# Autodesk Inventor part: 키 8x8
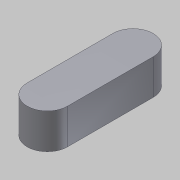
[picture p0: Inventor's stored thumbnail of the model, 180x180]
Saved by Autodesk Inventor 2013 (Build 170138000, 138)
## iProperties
Company: 한국ATC센터
Created: 2014-11
Part Number: 키 8x8
Document SubType Name: Modeling
Designer: KYOUNG IL JANG
Density: 7.86 g/cm^3
Material: Steel, Mild
Mass: 10.2483 g
Surface Area: 7.8646 cm^2
Volume: 1.30386 cm^3
Author: KYOUNG IL JANG
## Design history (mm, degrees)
sketch "스케치1"
  geometry: L1 (28.264, -14)-(28.264, -31) reference; L2 (20.264, -31)-(20.264, -14) reference; A1 r 4 centre (24.264, -31) between (20.264, -31) and (28.264, -31) reference; A2 r 4 centre (24.264, -14) between (28.264, -14) and (20.264, -14) reference; 1 further point
extrude "돌출1" new body sketch "스케치1" distance "d0" = 7; taper "d1" = 0 deg
node "솔리드1"
node "참조1"
